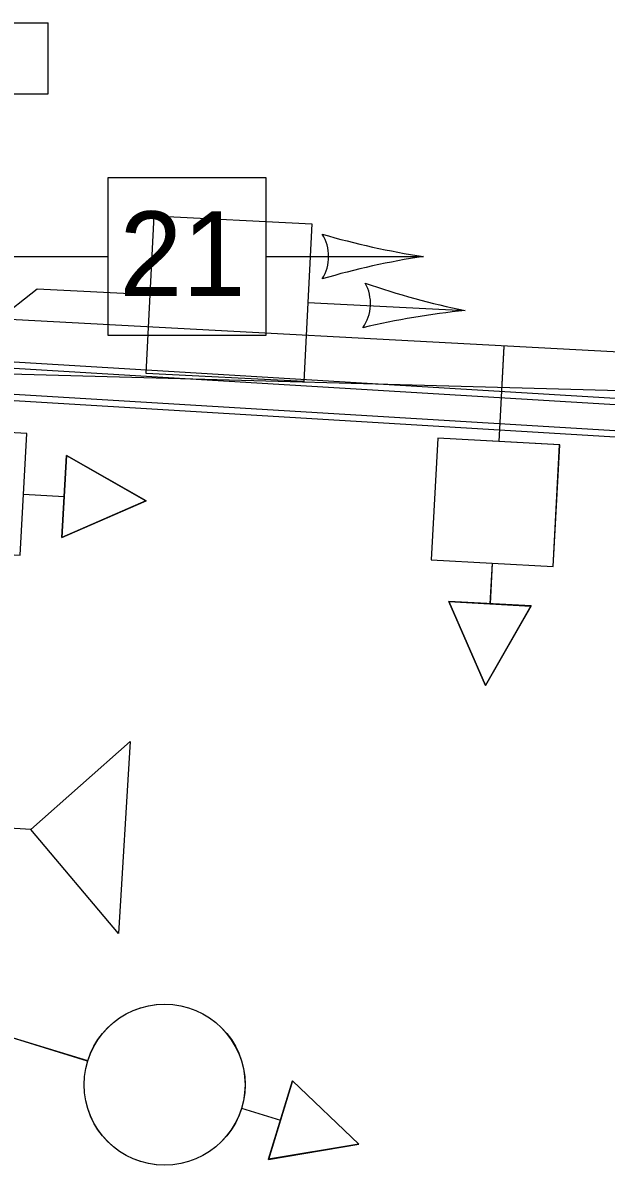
# Model space of a CAD drawing. Extents: x 647787 to 668496, y 640478 to 654412.
# Drawn here: x 662741.67 to 662764.06, y 647311.35 to 647355.2 of the extents above; entities that cross this region are included whole.
import ezdxf

# ---------------------------------------------------------------- set-up
doc = ezdxf.new("R2010")
doc.units = 0
for name, color, linetype in [('TEMP_SIGNAL POLES', 7, 'Continuous'), ('TEMP_SIGNAL_HEAD_STAGE 1A', 7, 'Continuous'), ('TEMP_SIGNAL_HEAD_STAGE 1B', 7, 'Continuous'), ('TEMP_SIGNAL_HEAD_STAGE 1C', 7, 'Continuous'), ('TEMP_SIGNAL_HEAD_STAGE 2', 7, 'Continuous'), ('TEMP_SIGNAL_HEAD_Stage 3', 7, 'Continuous'), ('TEMP_SIGNAL_HEAD_STAGE 5', 7, 'Continuous'), ('TEMP_SIGNAL_POLES_STAGE 1A', 7, 'Continuous'), ('TEMP_SIGNAL_POLES_STAGE 1B', 7, 'Continuous'), ('TEMP_SIGNAL_POLES_STAGE 1C', 7, 'Continuous'), ('TEMP_SIGNAL_POLES_STAGE 2', 7, 'Continuous'), ('TEMP_SIGNAL_POLES_STAGE 3', 7, 'Continuous'), ('TEMP_SIGNAL_POLES_STAGE 4', 7, 'Continuous'), ('TEMP_SIGNAL_POLES_STAGE 5', 7, 'Continuous'), ('TEXT_TEMP_SIGNAL_POLES_STAGE 2', 7, 'Continuous'), ('TEXT_TEMP_SIGNAL_POLES_STAGE 3', 7, 'Continuous'), ('TEXT_TEMP_SIGNAL_POLES_STAGE 4', 7, 'Continuous'), ('TEXT_TEMP_SIGNAL_POLES_STAGE 5', 7, 'Continuous')]:
    doc.layers.add(name, color=color, linetype=linetype)

msp = doc.modelspace()

# ---------------------------------------------------------------- linework, layer by layer
at = {"layer": 'TEMP_SIGNAL POLES'}
for p, q in [((662736.585, 647344.078), (662820.429, 647339.562)), ((662736.588, 647344.08), (662820.431, 647339.564))]:
    msp.add_line(p, q, dxfattribs=at)
at = {"layer": 'TEMP_SIGNAL_HEAD_STAGE 1A'}
for p, q in [((662739.457, 647355.203), (662742.644, 647355.203)), ((662739.457, 647355.203), (662742.644, 647355.203)), ((662742.644, 647352.474), (662742.644, 647355.203)), ((662742.644, 647352.474), (662742.644, 647355.203)), ((662739.457, 647352.474), (662742.644, 647352.474)), ((662739.457, 647352.474), (662742.644, 647352.474)), ((662740.593, 647346.234), (662744.94, 647346.234)), ((662751.003, 647346.234), (662757.044, 647346.234)), ((662732.383, 647342.483), (662816.383, 647337.405)), ((662732.399, 647342.733), (662816.398, 647337.654)), ((662816.291, 647336.158), (662732.308, 647341.236)), ((662816.307, 647336.408), (662732.323, 647341.485))]:
    msp.add_line(p, q, dxfattribs=at)
for points in [[(662744.94, 647343.202), (662744.94, 647349.266), (662751.003, 647349.266), (662751.003, 647343.202)], [(662737.153, 647339.694), (662736.9, 647335.021), (662741.573, 647334.768), (662741.826, 647339.441)], [(662737.155, 647339.696), (662736.902, 647335.023), (662741.575, 647334.77), (662741.828, 647339.443)], [(662762.272, 647339.006), (662757.598, 647339.259), (662757.345, 647334.586), (662762.018, 647334.332)], [(662762.274, 647339.007), (662757.601, 647339.26), (662757.348, 647334.587), (662762.021, 647334.334)], [(662746.397, 647336.85), (662743.342, 647338.596), (662743.172, 647335.444)], [(662746.4, 647336.852), (662743.345, 647338.598), (662743.174, 647335.446)], [(662759.427, 647329.761), (662761.173, 647332.816), (662758.022, 647332.987)], [(662759.43, 647329.763), (662761.176, 647332.818), (662758.024, 647332.988)], [(662754.563, 647312.161), (662752.018, 647314.592), (662751.093, 647311.574)], [(662754.565, 647312.163), (662752.021, 647314.594), (662751.096, 647311.576)]]:
    msp.add_lwpolyline(points, close=True, dxfattribs=at)
for points in [[(662760.133, 647342.784), (662759.935, 647339.132)], [(662760.135, 647342.786), (662759.937, 647339.134)], [(662743.172, 647335.444), (662743.342, 647338.596), (662746.397, 647336.85), (662743.172, 647335.444)], [(662743.174, 647335.446), (662743.345, 647338.598), (662746.4, 647336.852), (662743.174, 647335.446)], [(662741.699, 647337.105), (662743.257, 647337.02)], [(662741.702, 647337.106), (662743.259, 647337.022)], [(662759.682, 647334.459), (662759.598, 647332.901)], [(662759.684, 647334.461), (662759.6, 647332.903)], [(662758.022, 647332.987), (662761.173, 647332.816), (662759.427, 647329.761), (662758.022, 647332.987)], [(662758.024, 647332.988), (662761.176, 647332.818), (662759.43, 647329.763), (662758.024, 647332.988)], [(662744.158, 647315.35), (662740.851, 647316.369)], [(662744.16, 647315.352), (662740.853, 647316.37)], [(662751.093, 647311.574), (662752.018, 647314.592), (662754.563, 647312.161), (662751.093, 647311.574)], [(662751.096, 647311.576), (662752.021, 647314.594), (662754.565, 647312.163), (662751.096, 647311.576)], [(662750.064, 647313.54), (662751.556, 647313.083)], [(662750.067, 647313.542), (662751.558, 647313.085)]]:
    msp.add_lwpolyline(points, dxfattribs=at)
for centre in [(662747.11, 647314.441), (662747.112, 647314.443)]:
    msp.add_circle(centre, 3.089, dxfattribs=at)
for centre, radius, start, end in [((662751.777, 647346.233), 1.629, 328.1527, 31.8473), ((662761.455, 647375.373), 29.472, 253.6536, 261.3917), ((662761.455, 647317.093), 29.472, 98.6083, 106.3464)]:
    msp.add_arc(centre, radius, start, end, dxfattribs=at)
at = {"layer": 'TEMP_SIGNAL_HEAD_STAGE 1B'}
for p, q in [((662740.593, 647346.234), (662744.94, 647346.234)), ((662751.003, 647346.234), (662757.044, 647346.234))]:
    msp.add_line(p, q, dxfattribs=at)
for points in [[(662744.94, 647343.202), (662744.94, 647349.266), (662751.003, 647349.266), (662751.003, 647343.202)], [(662754.563, 647312.161), (662752.018, 647314.592), (662751.093, 647311.574)], [(662754.565, 647312.163), (662752.021, 647314.594), (662751.096, 647311.576)]]:
    msp.add_lwpolyline(points, close=True, dxfattribs=at)
for points in [[(662744.158, 647315.35), (662740.851, 647316.369)], [(662744.16, 647315.352), (662740.853, 647316.37)], [(662751.093, 647311.574), (662752.018, 647314.592), (662754.563, 647312.161), (662751.093, 647311.574)], [(662751.096, 647311.576), (662752.021, 647314.594), (662754.565, 647312.163), (662751.096, 647311.576)], [(662750.064, 647313.54), (662751.556, 647313.083)], [(662750.067, 647313.542), (662751.558, 647313.085)]]:
    msp.add_lwpolyline(points, dxfattribs=at)
for centre in [(662747.11, 647314.441), (662747.112, 647314.443)]:
    msp.add_circle(centre, 3.089, dxfattribs=at)
for centre, radius, start, end in [((662751.777, 647346.233), 1.629, 328.1527, 31.8473), ((662761.455, 647375.373), 29.472, 253.6536, 261.3917), ((662761.455, 647317.093), 29.472, 98.6083, 106.3464)]:
    msp.add_arc(centre, radius, start, end, dxfattribs=at)
at = {"layer": 'TEMP_SIGNAL_HEAD_STAGE 1C'}
for p, q in [((662740.593, 647346.234), (662744.94, 647346.234)), ((662751.003, 647346.234), (662757.044, 647346.234))]:
    msp.add_line(p, q, dxfattribs=at)
for points in [[(662744.94, 647343.202), (662744.94, 647349.266), (662751.003, 647349.266), (662751.003, 647343.202)], [(662754.563, 647312.161), (662752.018, 647314.592), (662751.093, 647311.574)], [(662754.565, 647312.163), (662752.021, 647314.594), (662751.096, 647311.576)]]:
    msp.add_lwpolyline(points, close=True, dxfattribs=at)
for points in [[(662744.158, 647315.35), (662740.851, 647316.369)], [(662744.16, 647315.352), (662740.853, 647316.37)], [(662751.093, 647311.574), (662752.018, 647314.592), (662754.563, 647312.161), (662751.093, 647311.574)], [(662751.096, 647311.576), (662752.021, 647314.594), (662754.565, 647312.163), (662751.096, 647311.576)], [(662750.064, 647313.54), (662751.556, 647313.083)], [(662750.067, 647313.542), (662751.558, 647313.085)]]:
    msp.add_lwpolyline(points, dxfattribs=at)
for centre in [(662747.11, 647314.441), (662747.112, 647314.443)]:
    msp.add_circle(centre, 3.089, dxfattribs=at)
for centre, radius, start, end in [((662751.777, 647346.233), 1.629, 328.1527, 31.8473), ((662761.455, 647375.373), 29.472, 253.6536, 261.3917), ((662761.455, 647317.093), 29.472, 98.6083, 106.3464)]:
    msp.add_arc(centre, radius, start, end, dxfattribs=at)
at = {"layer": 'TEMP_SIGNAL_HEAD_STAGE 2'}
for p, q in [((662740.593, 647346.234), (662744.94, 647346.234)), ((662751.003, 647346.234), (662757.044, 647346.234))]:
    msp.add_line(p, q, dxfattribs=at)
msp.add_lwpolyline([(662744.94, 647343.202), (662744.94, 647349.266), (662751.003, 647349.266), (662751.003, 647343.202)], close=True, dxfattribs=at)
for centre, radius, start, end in [((662751.777, 647346.233), 1.629, 328.1527, 31.8473), ((662761.455, 647375.373), 29.472, 253.6536, 261.3917), ((662761.455, 647317.093), 29.472, 98.6083, 106.3464)]:
    msp.add_arc(centre, radius, start, end, dxfattribs=at)
at = {"layer": 'TEMP_SIGNAL_HEAD_Stage 3'}
for p, q in [((662740.593, 647346.234), (662744.94, 647346.234)), ((662751.003, 647346.234), (662757.044, 647346.234))]:
    msp.add_line(p, q, dxfattribs=at)
msp.add_lwpolyline([(662744.94, 647343.202), (662744.94, 647349.266), (662751.003, 647349.266), (662751.003, 647343.202)], close=True, dxfattribs=at)
for centre, radius, start, end in [((662751.777, 647346.233), 1.629, 328.1527, 31.8473), ((662761.455, 647375.373), 29.472, 253.6536, 261.3917), ((662761.455, 647317.093), 29.472, 98.6083, 106.3464)]:
    msp.add_arc(centre, radius, start, end, dxfattribs=at)
at = {"layer": 'TEMP_SIGNAL_HEAD_STAGE 5'}
for p, q in [((662740.593, 647346.234), (662744.94, 647346.234)), ((662751.003, 647346.234), (662757.044, 647346.234))]:
    msp.add_line(p, q, dxfattribs=at)
msp.add_lwpolyline([(662744.94, 647343.202), (662744.94, 647349.266), (662751.003, 647349.266), (662751.003, 647343.202)], close=True, dxfattribs=at)
for centre, radius, start, end in [((662751.777, 647346.233), 1.629, 328.1527, 31.8473), ((662761.455, 647375.373), 29.472, 253.6536, 261.3917), ((662761.455, 647317.093), 29.472, 98.6083, 106.3464)]:
    msp.add_arc(centre, radius, start, end, dxfattribs=at)
at = {"layer": 'TEMP_SIGNAL_POLES_STAGE 1A'}
for p, q in [((662730.517, 647335.789), (662742.215, 647344.993)), ((662742.215, 647344.993), (662746.557, 647344.772)), ((662752.612, 647344.465), (662758.644, 647344.159)), ((662720.154, 647342.307), (662819.853, 647339.565))]:
    msp.add_line(p, q, dxfattribs=at)
msp.add_lwpolyline([(662746.403, 647341.744), (662746.71, 647347.8), (662752.765, 647347.493), (662752.458, 647341.436)], close=True, dxfattribs=at)
msp.add_lwpolyline([(662741.979, 647324.238), (662745.79, 647327.615), (662745.344, 647320.249), (662741.979, 647324.238), (662736.768, 647324.553)], dxfattribs=at)
for centre, radius, start, end in [((662753.385, 647344.425), 1.629, 325.247, 28.9416), ((662764.527, 647373.037), 29.472, 250.7478, 258.486), ((662761.573, 647314.832), 29.472, 95.7026, 103.4407)]:
    msp.add_arc(centre, radius, start, end, dxfattribs=at)
at = {"layer": 'TEMP_SIGNAL_POLES_STAGE 1B'}
msp.add_line((662720.154, 647342.307), (662819.853, 647339.565), dxfattribs=at)
at = {"layer": 'TEMP_SIGNAL_POLES_STAGE 1C'}
msp.add_line((662720.154, 647342.307), (662819.853, 647339.565), dxfattribs=at)
at = {"layer": 'TEMP_SIGNAL_POLES_STAGE 2'}
msp.add_line((662720.154, 647342.307), (662819.853, 647339.565), dxfattribs=at)
at = {"layer": 'TEMP_SIGNAL_POLES_STAGE 3'}
msp.add_line((662720.154, 647342.307), (662819.853, 647339.565), dxfattribs=at)
at = {"layer": 'TEMP_SIGNAL_POLES_STAGE 4'}
msp.add_line((662720.154, 647342.307), (662819.853, 647339.565), dxfattribs=at)
at = {"layer": 'TEMP_SIGNAL_POLES_STAGE 5'}
msp.add_line((662720.154, 647342.307), (662819.853, 647339.565), dxfattribs=at)

# ---------------------------------------------------------------- texts
at = {"layer": 'TEXT_TEMP_SIGNAL_POLES_STAGE 2'}
msp.add_text('21', height=3.25, dxfattribs=at).set_placement((662745.378, 647344.714))
msp.add_text('21', height=3.25, dxfattribs=at).set_placement((662745.378, 647344.714))
msp.add_text('21', height=3.25, dxfattribs=at).set_placement((662745.378, 647344.714))
msp.add_text('21', height=3.25, dxfattribs=at).set_placement((662745.378, 647344.714))
at = {"layer": 'TEXT_TEMP_SIGNAL_POLES_STAGE 3'}
msp.add_text('21', height=3.25, dxfattribs=at).set_placement((662745.378, 647344.714))
at = {"layer": 'TEXT_TEMP_SIGNAL_POLES_STAGE 4'}
msp.add_text('21', height=3.25, dxfattribs=at).set_placement((662745.378, 647344.714))
at = {"layer": 'TEXT_TEMP_SIGNAL_POLES_STAGE 5'}
msp.add_text('21', height=3.25, dxfattribs=at).set_placement((662745.378, 647344.714))

doc.saveas('drawing.dxf')
